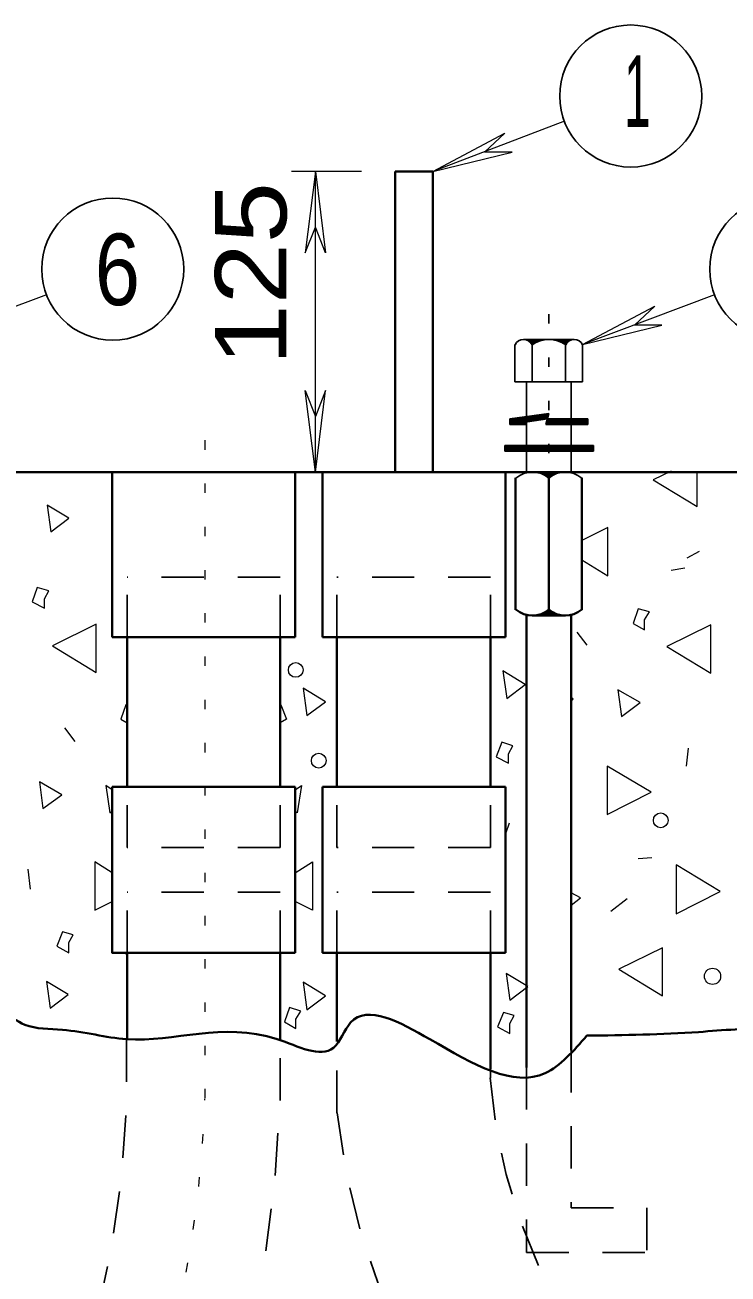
# Model space of a CAD drawing. Extents: x 312583 to 312854, y 144419 to 144597.
# Drawn here: x 312726.12 to 312733.6, y 144536.45 to 144549.74 of the extents above; entities that cross this region are included whole.
import ezdxf

# ---------------------------------------------------------------- set-up
doc = ezdxf.new("R2010")
doc.units = 0
doc.header["$LTSCALE"] = 0.3
doc.linetypes.add('DOTTED', pattern=[1.5, 0.3, -1.2])
doc.linetypes.add('SHORT_DASHED', pattern=[2.7, 1.5, -1.2])
doc.layers.add('1', color=7, linetype='Continuous', lineweight=25)
doc.layers.add('2', color=7, linetype='Continuous', lineweight=13)

msp = doc.modelspace()

# ---------------------------------------------------------------- linework, layer by layer
at = {"layer": '1', "lineweight": 40}
for p, q in [((312730.0581, 144548.1803), (312730.4568, 144548.1803)), ((312730.0581, 144548.1803), (312730.0581, 144544.9833)), ((312730.4568, 144548.1803), (312730.4568, 144544.9833)), ((312722.2688, 144544.9833), (312760.6021, 144544.9833)), ((312727.0451, 144543.2276), (312727.0451, 144544.9833)), ((312728.9925, 144543.2276), (312728.9925, 144544.9833)), ((312729.2838, 144543.2276), (312729.2838, 144544.9833)), ((312731.2311, 144543.2276), (312731.2311, 144544.9833)), ((312731.3385, 144544.9219), (312731.3385, 144543.5189)), ((312731.6911, 144544.9833), (312731.6911, 144543.4576)), ((312732.0438, 144544.9219), (312732.0438, 144543.5189)), ((312731.4535, 144543.4576), (312731.4535, 144538.6506)), ((312731.5148, 144543.4576), (312731.8675, 144543.4576)), ((312731.9288, 144543.4576), (312731.9288, 144538.8346)), ((312728.9925, 144543.2276), (312727.0451, 144543.2276)), ((312727.2061, 144541.6329), (312727.2061, 144543.2276)), ((312728.8315, 144541.6329), (312728.8315, 144543.2276)), ((312731.2311, 144543.2276), (312729.2838, 144543.2276)), ((312729.4371, 144541.6329), (312729.4371, 144543.2276)), ((312731.0701, 144541.6329), (312731.0701, 144543.2276)), ((312728.9925, 144541.6329), (312727.0451, 144541.6329)), ((312728.9925, 144539.8696), (312728.9925, 144541.6329)), ((312731.2311, 144541.6329), (312729.2838, 144541.6329)), ((312731.2311, 144539.8696), (312731.2311, 144541.6329)), ((312727.2061, 144538.9496), (312727.2061, 144539.8696)), ((312728.8315, 144538.9496), (312728.8315, 144539.8696)), ((312729.4371, 144538.9266), (312729.4371, 144539.8696)), ((312731.0701, 144538.6353), (312731.0701, 144539.8696))]:
    msp.add_line(p, q, dxfattribs=at)
at = {"layer": '1', "linetype": 'DOTTED'}
msp.add_line((312731.6911, 144546.6623), (312731.6911, 144544.9833), dxfattribs=at)
at = {"layer": '1'}
for p, q in [((312731.3308, 144546.3403), (312731.3308, 144545.9416)), ((312731.4228, 144546.3939), (312731.9595, 144546.3939)), ((312731.5148, 144546.3403), (312731.5148, 144545.9416)), ((312731.8675, 144546.3403), (312731.8675, 144545.9416)), ((312732.0515, 144546.3403), (312732.0515, 144545.9416)), ((312731.3308, 144545.9416), (312732.0515, 144545.9416)), ((312731.4535, 144545.9416), (312731.4535, 144544.9833)), ((312731.9288, 144545.9416), (312731.9288, 144544.9833)), ((312731.2771, 144545.5506), (312731.2771, 144545.4893)), ((312731.6758, 144545.5506), (312732.1051, 144545.5506)), ((312732.1051, 144545.5506), (312732.1051, 144545.4893)), ((312731.6605, 144545.4893), (312732.1051, 144545.4893)), ((312731.2235, 144545.2669), (312732.1665, 144545.2669)), ((312731.2235, 144545.2669), (312731.2235, 144545.2056)), ((312732.1665, 144545.2669), (312732.1665, 144545.2056)), ((312731.2235, 144545.2516), (312732.1665, 144545.2516)), ((312731.2235, 144545.2363), (312732.1665, 144545.2363)), ((312731.2235, 144545.2209), (312732.1665, 144545.2209)), ((312731.2235, 144545.2056), (312732.1665, 144545.2056)), ((312731.4535, 144544.9833), (312731.9288, 144544.9833)), ((312731.5148, 144544.9833), (312731.8675, 144544.9833))]:
    msp.add_line(p, q, dxfattribs=at)
at = {"layer": '1', "linetype": 'DOTTED', "lineweight": 13}
msp.add_line((312728.0341, 144538.3209), (312728.0341, 144545.4816), dxfattribs=at)
at = {"layer": '1', "linetype": 'SHORT_DASHED'}
for p, q in [((312728.8315, 144543.8639), (312727.2061, 144543.8639)), ((312727.2061, 144543.2276), (312727.2061, 144543.8639)), ((312728.8315, 144543.2276), (312728.8315, 144543.8639)), ((312731.0701, 144543.8639), (312729.4371, 144543.8639)), ((312729.4371, 144543.2276), (312729.4371, 144543.8639)), ((312731.0701, 144543.2276), (312731.0701, 144543.8639)), ((312727.2061, 144540.9889), (312727.2061, 144541.6329)), ((312728.8315, 144540.9889), (312728.8315, 144541.6329)), ((312729.4371, 144540.9889), (312729.4371, 144541.6329)), ((312731.0701, 144540.9889), (312731.0701, 144541.6329)), ((312728.8315, 144540.9889), (312727.2061, 144540.9889)), ((312731.0701, 144540.9889), (312729.4371, 144540.9889)), ((312728.8315, 144540.5136), (312727.2061, 144540.5136)), ((312727.2061, 144539.8696), (312727.2061, 144540.5136)), ((312728.8315, 144539.8696), (312728.8315, 144540.5136)), ((312731.0701, 144540.5136), (312729.4371, 144540.5136)), ((312729.4371, 144539.8696), (312729.4371, 144540.5136)), ((312731.0701, 144539.8696), (312731.0701, 144540.5136)), ((312729.6288, 144539.8696), (312729.4065, 144539.8696)), ((312728.8315, 144538.2979), (312728.8315, 144538.9419)), ((312729.4371, 144538.1676), (312729.4371, 144538.9266)), ((312731.9288, 144538.8346), (312731.9288, 144537.1556)), ((312731.0701, 144538.5356), (312731.0701, 144538.6353)), ((312731.4535, 144538.6506), (312731.4535, 144536.6803)), ((312731.4535, 144536.6803), (312732.7338, 144536.6803))]:
    msp.add_line(p, q, dxfattribs=at)
at = {"layer": '1'}
for points in [[(312731.4458, 144546.3939), (312731.6451, 144546.3939), (312731.6145, 144546.3863), (312731.5915, 144546.3786), (312731.5531, 144546.3633), (312731.5148, 144546.3403), (312731.4995, 144546.3633), (312731.4841, 144546.3786), (312731.4535, 144546.3939), (312731.6298, 144546.3939), (312731.5838, 144546.3786), (312731.5455, 144546.3633), (312731.5148, 144546.3479), (312731.4841, 144546.3709), (312731.4688, 144546.3863), (312731.6068, 144546.3863), (312731.5608, 144546.3709), (312731.5148, 144546.3479), (312731.4765, 144546.3863), (312731.5915, 144546.3863), (312731.5148, 144546.3556), (312731.4841, 144546.3863), (312731.5761, 144546.3863), (312731.5148, 144546.3556), (312731.4918, 144546.3786), (312731.5685, 144546.3786), (312731.5148, 144546.3633), (312731.4995, 144546.3786), (312731.5455, 144546.3786), (312731.5148, 144546.3709), (312731.5071, 144546.3786), (312731.5301, 144546.3786), (312731.5148, 144546.3709)], [(312731.9365, 144546.3939), (312731.7371, 144546.3939), (312731.7755, 144546.3863), (312731.7908, 144546.3786), (312731.8291, 144546.3633), (312731.8675, 144546.3403), (312731.8828, 144546.3633), (312731.8981, 144546.3786), (312731.9288, 144546.3939), (312731.7525, 144546.3939), (312731.8061, 144546.3786), (312731.8368, 144546.3633), (312731.8675, 144546.3479), (312731.8981, 144546.3709), (312731.9135, 144546.3863), (312731.7755, 144546.3863), (312731.8215, 144546.3709), (312731.8675, 144546.3479), (312731.9058, 144546.3863), (312731.7908, 144546.3863), (312731.8675, 144546.3556), (312731.8981, 144546.3863), (312731.8061, 144546.3863), (312731.8751, 144546.3556), (312731.8905, 144546.3786), (312731.8215, 144546.3786), (312731.8675, 144546.3633), (312731.8828, 144546.3786), (312731.8368, 144546.3786), (312731.8675, 144546.3709), (312731.8751, 144546.3786), (312731.8521, 144546.3786), (312731.8675, 144546.3709)], [(312731.2771, 144545.5506), (312731.6911, 144545.6043), (312731.6605, 144545.4893)], [(312731.4535, 144545.4893), (312731.2771, 144545.4969), (312731.2848, 144545.5429), (312731.6835, 144545.5966), (312731.6681, 144545.5506), (312731.4535, 144545.5199), (312731.4458, 144545.4969), (312731.2848, 144545.5046), (312731.2925, 144545.5353), (312731.6681, 144545.5889), (312731.6605, 144545.5583), (312731.4381, 144545.5199), (312731.4381, 144545.5046), (312731.2925, 144545.5123), (312731.2925, 144545.5276), (312731.6528, 144545.5813), (312731.6528, 144545.5659), (312731.4458, 144545.5276), (312731.4305, 144545.5199), (312731.3845, 144545.5123), (312731.3001, 144545.5199), (312731.6451, 144545.5736), (312731.3538, 144545.5199)], [(312731.6758, 144545.5506), (312731.2771, 144545.4893), (312731.4535, 144545.4893)], [(312731.6681, 144545.4969), (312732.0975, 144545.4969), (312732.0975, 144545.5429), (312731.6835, 144545.5353), (312731.6681, 144545.5046), (312732.0898, 144545.5046), (312732.0898, 144545.5353), (312731.6835, 144545.5276), (312731.6758, 144545.5123), (312732.0821, 144545.5123), (312732.0745, 144545.5276), (312732.0745, 144545.5276), (312731.6911, 144545.5276), (312731.6835, 144545.5199), (312732.0745, 144545.5199)], [(312731.5608, 144544.9833), (312731.8215, 144544.9833), (312731.7908, 144544.9756), (312731.7678, 144544.9679), (312731.7371, 144544.9526), (312731.7218, 144544.9449), (312731.6911, 144544.9296), (312731.6911, 144544.9219), (312731.6451, 144544.9603), (312731.5991, 144544.9756), (312731.5761, 144544.9756), (312731.8061, 144544.9833), (312731.7831, 144544.9756), (312731.7678, 144544.9756), (312731.7371, 144544.9603), (312731.7065, 144544.9449), (312731.6988, 144544.9373), (312731.6911, 144544.9296), (312731.6451, 144544.9603), (312731.5991, 144544.9756), (312731.7678, 144544.9756), (312731.7295, 144544.9603), (312731.6911, 144544.9373), (312731.6145, 144544.9756), (312731.7525, 144544.9756), (312731.6911, 144544.9373), (312731.6298, 144544.9679), (312731.7448, 144544.9756), (312731.6988, 144544.9449), (312731.6528, 144544.9679), (312731.7218, 144544.9679), (312731.6911, 144544.9603), (312731.6528, 144544.9603), (312731.6758, 144544.9526), (312731.6835, 144544.9679), (312731.6911, 144544.9449), (312731.7065, 144544.9603), (312731.7141, 144544.9603), (312731.7295, 144544.9679)]]:
    msp.add_lwpolyline(points, dxfattribs=at)
at = {"layer": '1', "lineweight": 40}
for points in [[(312731.5608, 144543.4576), (312731.8215, 144543.4576), (312731.7908, 144543.4653), (312731.7678, 144543.4729), (312731.7371, 144543.4883), (312731.7218, 144543.4959), (312731.6911, 144543.5113), (312731.6911, 144543.5189), (312731.6451, 144543.4806), (312731.5991, 144543.4653), (312731.5761, 144543.4653), (312731.8061, 144543.4576), (312731.7831, 144543.4653), (312731.7678, 144543.4653), (312731.7371, 144543.4806), (312731.7065, 144543.4959), (312731.6988, 144543.5036), (312731.6911, 144543.5113), (312731.6451, 144543.4806), (312731.5991, 144543.4653), (312731.7678, 144543.4653), (312731.7295, 144543.4806), (312731.6911, 144543.5036), (312731.6145, 144543.4653), (312731.7525, 144543.4653), (312731.6911, 144543.5036), (312731.6298, 144543.4729), (312731.7448, 144543.4653), (312731.6988, 144543.4959), (312731.6528, 144543.4729), (312731.7218, 144543.4729), (312731.6911, 144543.4806), (312731.6528, 144543.4729), (312731.6758, 144543.4883), (312731.6835, 144543.4729), (312731.6911, 144543.4959), (312731.7065, 144543.4806), (312731.7141, 144543.4806), (312731.7295, 144543.4729)], [(312728.9925, 144539.8696), (312727.0451, 144539.8696), (312727.0451, 144541.6329)], [(312731.2311, 144539.8696), (312729.2838, 144539.8696), (312729.2838, 144541.6329)]]:
    msp.add_lwpolyline(points, dxfattribs=at)
at = {"layer": '1', "linetype": 'SHORT_DASHED'}
msp.add_lwpolyline([(312731.9288, 144537.1556), (312732.7338, 144537.1556), (312732.7338, 144536.6803)], dxfattribs=at)
at = {"layer": '1'}
for centre, radius, start, end in [((312731.4231, 144546.2937), 0.0993, 25.60064, 154.39936), ((312731.6918, 144546.0804), 0.3126, 55.04559, 124.95441), ((312731.9604, 144546.2937), 0.0993, 25.60064, 154.39936), ((312731.517, 144544.7112), 0.272, 50.00693, 129.99306), ((312731.8665, 144544.7112), 0.272, 50.00694, 129.99307)]:
    msp.add_arc(centre, radius, start, end, dxfattribs=at)
at = {"layer": '1', "lineweight": 40}
for centre, start, end in [((312731.517, 144543.7285), 230.00694, 309.99307), ((312731.8665, 144543.7285), 230.00693, 309.99306)]:
    msp.add_arc(centre, 0.272, start, end, dxfattribs=at)
at = {"layer": '1', "linetype": 'SHORT_DASHED'}
for centre, radius, start, end in [((312716.5182, 144538.6104), 10.6854, 298.57546, 1.79804), ((312736.8038, 144538.9545), 5.75, 184.14986, 265.21724), ((312716.5182, 144538.6104), 12.3146, 294.52268, 358.54105), ((312736.7767, 144538.9543), 7.3792, 186.13, 266.47596)]:
    msp.add_arc(centre, radius, start, end, dxfattribs=at)
at = {"layer": '1', "linetype": 'DOTTED', "lineweight": 13}
msp.add_arc((312716.5182, 144538.6104), 11.516, 273.77656, 358.54081, dxfattribs=at)
at = {"layer": '1', "lineweight": 40}
for points in [[(312723.1581, 144544.9679), (312723.3651, 144544.3469), (312723.4495, 144541.7403), (312723.9095, 144541.0349), (312724.4231, 144540.5826), (312724.9828, 144540.0689), (312725.6805, 144539.5016), (312726.1175, 144539.1029), (312726.5161, 144539.0493), (312727.1985, 144538.9496), (312728.8008, 144538.9496), (312729.3988, 144538.8576), (312729.5828, 144539.1259), (312730.4261, 144538.9496), (312731.6528, 144538.5893), (312732.0975, 144538.9879)], [(312732.0975, 144538.9879), (312733.2858, 144539.0263), (312734.0678, 144539.0416), (312735.4631, 144538.8653), (312735.9385, 144539.0646), (312736.7971, 144538.9266), (312737.6711, 144538.5893), (312738.7675, 144538.3286), (312739.6108, 144538.3899), (312740.0478, 144538.4666), (312740.3468, 144538.3439), (312740.6611, 144538.2826)]]:
    msp.add_spline(points, degree=3, dxfattribs=at)
at = {"layer": '2'}
for p, q in [((312731.8598, 144548.7169), (312730.4568, 144548.1803)), ((312730.4568, 144548.1803), (312731.2235, 144548.5866)), ((312731.2235, 144548.5866), (312731.0088, 144548.3873)), ((312730.4568, 144548.1803), (312731.3001, 144548.3873)), ((312731.3001, 144548.3873), (312731.0088, 144548.3873)), ((312729.6978, 144548.1803), (312728.9541, 144548.1803)), ((312729.2071, 144548.1803), (312729.0998, 144547.3139)), ((312729.2071, 144544.9833), (312729.2071, 144548.1803)), ((312729.2071, 144548.1803), (312729.3145, 144547.3139)), ((312729.0998, 144547.3139), (312729.2071, 144547.5899)), ((312729.3145, 144547.3139), (312729.2071, 144547.5899)), ((312726.3475, 144546.8693), (312724.9445, 144546.3403)), ((312733.4545, 144546.8693), (312732.0515, 144546.3403)), ((312732.0515, 144546.3403), (312732.8181, 144546.7466)), ((312732.8181, 144546.7466), (312732.6035, 144546.5473)), ((312732.0515, 144546.3403), (312732.8948, 144546.5473)), ((312732.8948, 144546.5473), (312732.6035, 144546.5473)), ((312729.0998, 144545.8496), (312729.2071, 144545.5736)), ((312729.2071, 144544.9833), (312729.0998, 144545.8496)), ((312729.3145, 144545.8496), (312729.2071, 144545.5736)), ((312729.2071, 144544.9833), (312729.3145, 144545.8496)), ((312733.2705, 144544.6153), (312733.2705, 144544.9909)), ((312733.1631, 144544.0709), (312733.2935, 144544.1399)), ((312732.0438, 144544.0479), (312732.3198, 144543.8793)), ((312732.9945, 144543.9406), (312733.1401, 144543.9636)), ((312731.9901, 144543.2813), (312732.0975, 144543.1433)), ((312726.5391, 144542.2616), (312726.6465, 144542.1159)), ((312733.1555, 144541.8553), (312733.1785, 144542.0469)), ((312727.0221, 144541.3569), (312727.0451, 144541.3799)), ((312729.0155, 144541.3569), (312728.9925, 144541.3799)), ((312731.2695, 144541.2496), (312731.2311, 144541.1346)), ((312732.6418, 144540.8739), (312732.7875, 144540.8816)), ((312726.1481, 144540.7589), (312726.1711, 144540.5443)), ((312727.0451, 144540.7206), (312726.8611, 144540.8356)), ((312728.9925, 144540.7206), (312729.1765, 144540.8356)), ((312732.5268, 144540.4446), (312732.3505, 144540.3066)), ((312727.1908, 144539.8543), (312727.2061, 144539.8543)), ((312728.8391, 144539.8543), (312728.8315, 144539.8543))]:
    msp.add_line(p, q, dxfattribs=at)
for points in [[(312732.9945, 144544.9909), (312732.8028, 144544.8989), (312733.2705, 144544.6153)], [(312732.3198, 144543.8793), (312732.3198, 144544.3929), (312732.0438, 144544.2549)], [(312727.2061, 144542.4993), (312727.1908, 144542.5069), (312727.1371, 144542.3536), (312727.2061, 144542.3153)], [(312728.8315, 144542.4993), (312728.8391, 144542.5069), (312728.9005, 144542.3536), (312728.8315, 144542.3153)], [(312731.9288, 144542.5529), (312731.9518, 144542.5683), (312731.9288, 144542.5836)], [(312727.0451, 144541.6023), (312726.9761, 144541.6483), (312727.0221, 144541.3569)], [(312728.9925, 144541.6023), (312729.0615, 144541.6483), (312729.0155, 144541.3569)], [(312726.8611, 144540.8356), (312726.8611, 144540.3219), (312727.0451, 144540.4139)], [(312729.1765, 144540.8356), (312729.1765, 144540.3219), (312728.9925, 144540.4139)], [(312731.9288, 144540.3756), (312732.0285, 144540.4523), (312731.9288, 144540.5059)]]:
    msp.add_lwpolyline(points, dxfattribs=at)
for points in [[(312726.3935, 144544.3469), (312726.5851, 144544.4926), (312726.3551, 144544.6306)], [(312726.3245, 144543.6339), (312726.3705, 144543.7183), (312726.2478, 144543.7566), (312726.1941, 144543.6033), (312726.3245, 144543.5343)], [(312732.7108, 144543.4116), (312732.7645, 144543.4959), (312732.6418, 144543.5266), (312732.5881, 144543.3733), (312732.7108, 144543.3043)], [(312726.8765, 144542.8519), (312726.8765, 144543.3656), (312726.4088, 144543.1356)], [(312733.4161, 144542.8443), (312733.4161, 144543.3579), (312732.9485, 144543.1279)], [(312731.2465, 144542.5759), (312731.4381, 144542.7216), (312731.2005, 144542.8673)], [(312729.1151, 144542.3919), (312729.3145, 144542.5376), (312729.0768, 144542.6833)], [(312732.4655, 144542.3843), (312732.6648, 144542.5299), (312732.4271, 144542.6679)], [(312731.2618, 144541.9856), (312731.3078, 144542.0699), (312731.1928, 144542.1083), (312731.1315, 144541.9549), (312731.2618, 144541.8859)], [(312732.3121, 144541.8553), (312732.3121, 144541.3416), (312732.7798, 144541.5793)], [(312726.3091, 144541.4029), (312726.5085, 144541.5486), (312726.2708, 144541.6866)], [(312733.0481, 144540.8049), (312733.0481, 144540.2836), (312733.5158, 144540.5213)], [(312726.5851, 144539.9769), (312726.6311, 144540.0613), (312726.5161, 144540.0919), (312726.4548, 144539.9386), (312726.5851, 144539.8696)], [(312732.9025, 144539.4096), (312732.9025, 144539.9233), (312732.4348, 144539.6933)], [(312726.3858, 144539.2793), (312726.5775, 144539.4249), (312726.3475, 144539.5629)], [(312729.1151, 144539.2639), (312729.3145, 144539.4096), (312729.0768, 144539.5553)], [(312731.2771, 144539.3636), (312731.4688, 144539.5093), (312731.2388, 144539.6473)], [(312729.0001, 144539.1643), (312729.0538, 144539.2486), (312728.9311, 144539.2869), (312728.8775, 144539.1336), (312729.0001, 144539.0646)], [(312731.2771, 144539.1183), (312731.3231, 144539.2026), (312731.2081, 144539.2333), (312731.1468, 144539.0799), (312731.2771, 144539.0109)]]:
    msp.add_lwpolyline(points, close=True, dxfattribs=at)
at = {"layer": '2', "lineweight": 25}
for centre in [(312732.5632, 144548.9833), (312727.0509, 144547.1421), (312734.1592, 144547.1421)]:
    msp.add_circle(centre, 0.7557, dxfattribs=at)
at = {"layer": '2'}
for centre, radius in [((312728.9985, 144542.8785), 0.0784), ((312729.2432, 144541.9132), 0.0784), ((312732.8829, 144541.2781), 0.0784), ((312733.4335, 144539.619), 0.0865)]:
    msp.add_circle(centre, radius, dxfattribs=at)

# ---------------------------------------------------------------- texts
for s, width, p in [('1', 0.5, (312732.4926, 144548.6553)), ('6', 0.85, (312726.8608, 144546.7592))]:
    msp.add_text(s, height=0.76, dxfattribs=dict(at, width=width)).set_placement(p)
at = {"layer": '2', "width": 1.15}
msp.add_text('125 ', height=0.76, rotation=90, dxfattribs=at).set_placement((312728.8999, 144546.1173))

doc.saveas('drawing.dxf')
